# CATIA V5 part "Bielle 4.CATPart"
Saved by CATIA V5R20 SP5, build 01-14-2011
Part number: Bielle 4
Bounding box of the stored display mesh (mm): x -210 to 10, y -260 to -240, z -25 to -15
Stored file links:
  U:\CFAO\Thinkmotion\Bielle 4.CATPart
  U:\CFAO\Thinkmotion\Bras Articule.CATProduct
  U:\CFAO\Thinkmotion\Squelette Bielle 3.CATPart
  U:\CFAO\Thinkmotion\Bielle 3.CATPart
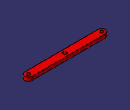
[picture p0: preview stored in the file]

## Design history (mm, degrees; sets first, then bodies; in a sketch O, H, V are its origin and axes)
Set1
  Plane1: linked copy from another document
  Point1: linked copy from another document
  Point2: linked copy from another document
  Line1: linked copy from another document
  Point3: linked copy from another document
Body1 (main body)
  Sketch1 on Plane1, origin (0, 0, -20), H (1, 0, 0), V (0, 1, 0)
    point P1 (0, -240)
    line L1 (0, -240) -> (-200, -240)
    arc A1 centre (-200, -250) radius 10 from (-200, -240) to (-200, -260) ccw
    point P3 (-200, -250)
    line L2 (-200, -260) -> (0, -260)
    point P5 (0, -260)
    arc A2 centre (0, -250) radius 10 from (0, -260) to (0, -240) ccw
    point P6 (0, -250)
    reference projected point E1 (-200, -250) from Point1
    reference projected point E2 (0, -250) from Point2
    reference projected line E3 (0, -250) -> (-100, -250) from Line1
    circle A3 centre (0, -250) radius 5
    circle A4 centre (-200, -250) radius 5
    circle A5 centre (-100, -250) radius 5
    reference projected point E4 (-100, -250) from Point3
    radius A2 = 10
    radius A4 = 5
    radius A3 = 5
    radius A5 = 5
    coincidence: P1 V, P5 V, P3 E1, E2 P6
    horizontal: L1 H
    tangency: A1 L1, L2 A1, A2 L1, A2 L2
    symmetry: L1 L2 E3
    concentricity: A4 A1, A3 A2, E4 A5
  Pad1: profile Sketch1, direction (0, 0, 1), length 5, mirrored extent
